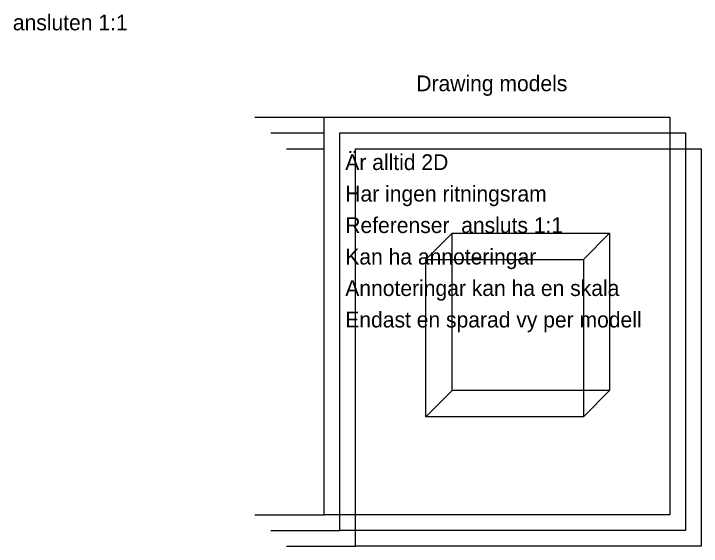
# Model space of a CAD drawing. Extents: x 1517691.1 to 1517704.2, y 6495357 to 6495367.2.
import ezdxf

# ---------------------------------------------------------------- set-up
doc = ezdxf.new("R2010")
doc.units = 0
for name, color, linetype in [('Default', 7, 'Continuous'), ('Design model', 7, 'Continuous'), ('Drawing model', 7, 'Continuous')]:
    doc.layers.add(name, color=color, linetype=linetype)

msp = doc.modelspace()

# ---------------------------------------------------------------- linework, layer by layer
at = {"layer": 'Default'}
for p, q in [((1517695.689, 6495365.181), (1517697.005, 6495365.181)), ((1517695.989, 6495364.881), (1517697.005, 6495364.881)), ((1517696.289, 6495364.581), (1517697.005, 6495364.581)), ((1517695.689, 6495357.607), (1517697.005, 6495357.607)), ((1517695.989, 6495357.307), (1517697.305, 6495357.307)), ((1517696.289, 6495357.007), (1517697.605, 6495357.007))]:
    msp.add_line(p, q, dxfattribs=at)
at = {"layer": 'Design model'}
for p, q in [((1517698.941, 6495362.472), (1517699.441, 6495362.972)), ((1517699.441, 6495362.972), (1517702.441, 6495362.972)), ((1517699.441, 6495359.972), (1517699.441, 6495362.972)), ((1517701.941, 6495362.472), (1517702.441, 6495362.972)), ((1517702.441, 6495362.972), (1517702.441, 6495359.972)), ((1517698.941, 6495362.472), (1517701.941, 6495362.472)), ((1517698.941, 6495359.472), (1517698.941, 6495362.472)), ((1517701.941, 6495362.472), (1517701.941, 6495359.472)), ((1517699.441, 6495359.972), (1517698.941, 6495359.472)), ((1517702.441, 6495359.972), (1517699.441, 6495359.972)), ((1517701.941, 6495359.472), (1517702.441, 6495359.972)), ((1517701.941, 6495359.472), (1517698.941, 6495359.472))]:
    msp.add_line(p, q, dxfattribs=at)
at = {"layer": 'Drawing model'}
for points in [[(1517697.005, 6495365.181), (1517703.585, 6495365.181), (1517703.585, 6495357.607), (1517697.005, 6495357.607)], [(1517697.305, 6495364.881), (1517703.885, 6495364.881), (1517703.885, 6495357.307), (1517697.305, 6495357.307)], [(1517697.605, 6495364.581), (1517704.185, 6495364.581), (1517704.185, 6495357.007), (1517697.605, 6495357.007)]]:
    msp.add_lwpolyline(points, close=True, dxfattribs=at)

# ---------------------------------------------------------------- texts
at = {"layer": 'Default'}
for s, p in [('ansluten 1:1', (1517691.079, 6495366.837)), ('Är alltid 2D', (1517697.408, 6495364.175)), ('Har ingen ritningsram', (1517697.408, 6495363.575)), ('Referenser  ansluts 1:1', (1517697.408, 6495362.975)), ('Kan ha annoteringar', (1517697.408, 6495362.375)), ('Annoteringar kan ha en skala', (1517697.408, 6495361.775)), ('Endast en sparad vy per modell', (1517697.408, 6495361.175))]:
    msp.add_text(s, height=0.3, dxfattribs=at).set_placement(p)
at = {"layer": 'Drawing model'}
msp.add_text('Drawing models', height=0.3, dxfattribs=at).set_placement((1517698.76, 6495365.677))

doc.saveas('drawing.dxf')
